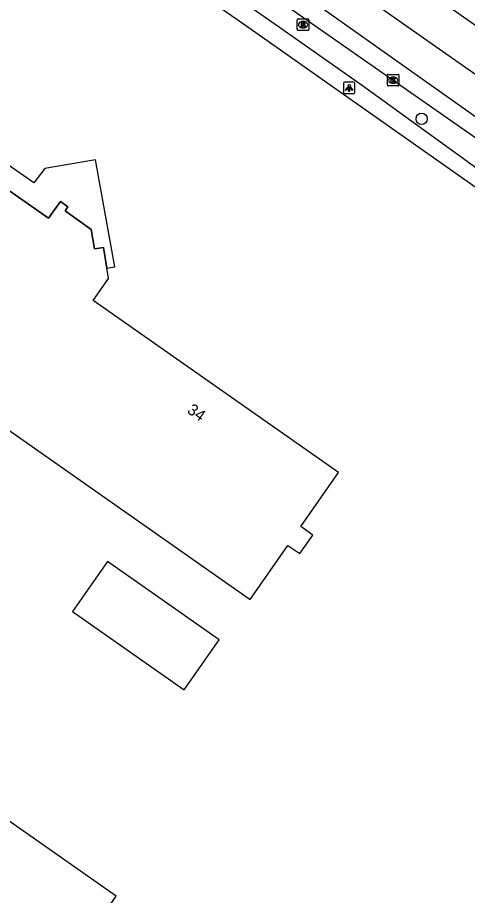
# Model space of a CAD drawing. Extents: x 155018 to 156648, y 383980 to 385733.
# Drawn here: x 155434.7 to 155473.7, y 385174.7 to 385250.7 of the extents above; entities that cross this region are included whole.
import ezdxf

# ---------------------------------------------------------------- set-up
doc = ezdxf.new("R2010")
doc.units = 0
for name, color, linetype in [('IMGEO_Boom', 7, 'Continuous'), ('IMGEO_Kolk', 7, 'Continuous'), ('IMGEO_Lichtpunt', 7, 'Continuous'), ('IMGEO_OVBaan_gesloten', 7, 'Continuous'), ('IMGEO_Pand', 7, 'Continuous'), ('IMGEO_Pand_nummerreeks', 7, 'Continuous'), ('IMGEO_Pand_overbouw', 7, 'Continuous'), ('IMGEO_Rijbaan_lokaal_gesloten', 7, 'Continuous'), ('IMGEO_Rioolput', 7, 'Continuous'), ('IMGEO_Voetpad_open', 7, 'Continuous')]:
    doc.layers.add(name, color=color, linetype=linetype)

msp = doc.modelspace()

# ---------------------------------------------------------------- linework, layer by layer
at = {"layer": 'IMGEO_Boom'}
msp.add_circle((155469.734, 385241.975), 0.489, dxfattribs=at)
at = {"layer": 'IMGEO_Kolk'}
for p, q in [((155466.764, 385244.9), (155466.764, 385245.752)), ((155466.839, 385245.826), (155467.691, 385245.826)), ((155467.252, 385245.606), (155467.277, 385245.606)), ((155467.765, 385245.752), (155467.765, 385244.9)), ((155467.691, 385244.826), (155466.839, 385244.826)), ((155467.275, 385245.046), (155467.25, 385245.046))]:
    msp.add_line(p, q, dxfattribs=at)
for points in [[(155466.764, 385244.9), (155466.764, 385245.752)], [(155466.839, 385245.826), (155467.691, 385245.826)], [(155467.085, 385245.526), (155467.208, 385245.526), (155467.208, 385245.375), (155467.338, 385245.526), (155467.502, 385245.526), (155467.356, 385245.375), (155467.509, 385245.126), (155467.357, 385245.126), (155467.272, 385245.29), (155467.208, 385245.223), (155467.208, 385245.126), (155467.085, 385245.126), (155467.085, 385245.526)], [(155467.765, 385245.752), (155467.765, 385244.9)], [(155467.691, 385244.826), (155466.839, 385244.826)]]:
    msp.add_lwpolyline(points, dxfattribs=at)
for centre, start, end in [((155466.841, 385245.75), 91.55205, 178.44795), ((155466.841, 385245.75), 91.55205, 178.44795), ((155467.689, 385245.75), 1.55205, 88.44795), ((155467.689, 385245.75), 1.55205, 88.44795), ((155466.841, 385244.902), 181.55205, 268.44795), ((155466.841, 385244.902), 181.55205, 268.44795), ((155467.689, 385244.902), 271.55205, 358.44795), ((155467.689, 385244.902), 271.55205, 358.44795)]:
    msp.add_arc(centre, 0.0765, start, end, dxfattribs=at)
for centre, major_axis, ratio, start_param, end_param in [((155467.251, 385245.326), (-0.387, 0.002), 0.722429, 4.712389, 7.853982), ((155467.276, 385245.326), (-0.39, 0.002), 0.717154, 1.570796, 4.712389)]:
    msp.add_ellipse(centre, major_axis=major_axis, ratio=ratio, start_param=start_param, end_param=end_param, dxfattribs=at)
at = {"layer": 'IMGEO_Lichtpunt'}
for p, q in [((155462.958, 385245.061), (155462.958, 385244.254)), ((155462.958, 385245.061), (155462.958, 385244.254)), ((155463.86, 385245.156), (155463.052, 385245.156)), ((155463.86, 385245.156), (155463.052, 385245.156)), ((155463.954, 385244.254), (155463.954, 385245.061)), ((155463.954, 385244.254), (155463.954, 385245.061)), ((155463.052, 385244.16), (155463.86, 385244.16)), ((155463.052, 385244.16), (155463.86, 385244.16))]:
    msp.add_line(p, q, dxfattribs=at)
for points in [[(155463.332, 385244.725), (155463.371, 385244.697), (155463.183, 385244.435), (155463.145, 385244.462), (155463.332, 385244.725)], [(155463.434, 385244.677), (155463.481, 385244.677), (155463.481, 385244.355), (155463.434, 385244.355), (155463.434, 385244.677)], [(155463.544, 385244.697), (155463.582, 385244.724), (155463.769, 385244.462), (155463.73, 385244.434), (155463.544, 385244.697)]]:
    msp.add_lwpolyline(points, dxfattribs=at)
msp.add_circle((155463.457, 385244.859), 0.0994, dxfattribs=at)
for centre, start, end in [((155463.052, 385245.061), 90, 180), ((155463.052, 385245.061), 90, 180), ((155463.86, 385245.061), 0, 90), ((155463.86, 385245.061), 0, 90), ((155463.052, 385244.254), 180, 270), ((155463.052, 385244.254), 180, 270), ((155463.86, 385244.254), 270, 0), ((155463.86, 385244.254), 270, 360)]:
    msp.add_arc(centre, 0.0946, start, end, dxfattribs=at)
at = {"layer": 'IMGEO_OVBaan_gesloten'}
for points in [[(155434.788, 385277.655), (155445.154, 385270.546), (155474.522, 385250), (155483.762, 385243.536)], [(155432.913, 385274.986), (155468.446, 385250), (155481.766, 385240.688)]]:
    msp.add_lwpolyline(points, dxfattribs=at)
at = {"layer": 'IMGEO_Pand'}
for points in [[(155441.261, 385226.23), (155442.591, 385228.15), (155442.443, 385229.05), (155442.151, 385230.83), (155441.388, 385230.704), (155441.107, 385232.405), (155438.832, 385234.02), (155439.081, 385234.37), (155438.441, 385234.81), (155437.391, 385233.36), (155423.311, 385243.23)], [(155430.523, 385217.398), (155454.872, 385200.35), (155458.13, 385205.01), (155459.18, 385204.32), (155460.31, 385205.93), (155459.27, 385206.67), (155462.53, 385211.34), (155441.261, 385226.23)], [(155439.481, 385199.296), (155449.162, 385192.518), (155452.199, 385196.856), (155442.519, 385203.634), (155439.481, 385199.296)], [(155442.008, 385172.848), (155443.274, 385174.657), (155413.901, 385195.202), (155370.632, 385133.346), (155367.766, 385129.249), (155364.489, 385131.542), (155359.431, 385135.082), (155348.617, 385119.628), (155349.496, 385119.02), (155349.893, 385116.961), (155349.266, 385116.068), (155368.071, 385102.911), (155368.632, 385103.714), (155385.157, 385092.221), (155424.544, 385148.026), (155428.297, 385153.343)]]:
    msp.add_lwpolyline(points, dxfattribs=at)
at = {"layer": 'IMGEO_Pand_overbouw'}
msp.add_lwpolyline([(155442.443, 385229.05), (155443.141, 385229.16), (155441.481, 385238.42), (155437.071, 385237.68), (155436.131, 385236.42), (155424.321, 385244.66), (155423.311, 385243.23), (155437.391, 385233.36), (155438.441, 385234.81), (155439.081, 385234.37), (155438.832, 385234.02), (155441.107, 385232.405), (155441.388, 385230.704), (155442.151, 385230.83)], close=True, dxfattribs=at)
at = {"layer": 'IMGEO_Rijbaan_lokaal_gesloten'}
for points in [[(155431.663, 385273.213), (155433.364, 385271.333), (155433.769, 385270.941), (155434.968, 385270.089), (155475.915, 385241.101)], [(155437.905, 385265.859), (155439.338, 385264.844), (155453.681, 385254.836), (155467.265, 385245.326), (155475.085, 385239.875)]]:
    msp.add_lwpolyline(points, dxfattribs=at)
at = {"layer": 'IMGEO_Rioolput'}
for p, q in [((155458.958, 385249.713), (155458.958, 385250.565)), ((155459.033, 385250.639), (155459.885, 385250.639)), ((155459.446, 385250.419), (155459.471, 385250.419)), ((155459.959, 385250.565), (155459.959, 385249.713)), ((155459.885, 385249.639), (155459.033, 385249.639)), ((155459.469, 385249.859), (155459.444, 385249.859))]:
    msp.add_line(p, q, dxfattribs=at)
for points in [[(155458.958, 385249.713), (155458.958, 385250.565)], [(155459.033, 385250.639), (155459.885, 385250.639)], [(155459.547, 385250.337), (155459.295, 385250.339), (155459.295, 385249.939)], [(155459.295, 385249.939), (155459.419, 385249.939), (155459.419, 385250.101), (155459.43, 385250.101)], [(155459.473, 385250.258), (155459.419, 385250.258), (155459.419, 385250.177)], [(155459.419, 385250.177), (155459.471, 385250.177)], [(155459.959, 385250.565), (155459.959, 385249.713)], [(155459.885, 385249.639), (155459.033, 385249.639)], [(155459.477, 385250.072), (155459.548, 385249.939), (155459.688, 385249.939), (155459.623, 385250.065)]]:
    msp.add_lwpolyline(points, dxfattribs=at)
for centre, radius, start, end in [((155459.035, 385250.563), 0.0765, 91.55205, 178.44795), ((155459.035, 385250.563), 0.0765, 91.55205, 178.44795), ((155459.429, 385250.048), 0.0533, 26.02933, 88.69889), ((155459.455, 385250.366), 0.19, 274.7715, 282.96867), ((155459.479, 385250.162), 0.0964, 77.00612, 93.18647), ((155459.493, 385250.219), 0.0378, 276.66336, 79.67722), ((155459.546, 385250.227), 0.109, 350.36119, 89.41601), ((155459.544, 385250.227), 0.112, 277.58423, 350.98172), ((155459.528, 385250.012), 0.108, 29.51342, 73.79051), ((155459.883, 385250.563), 0.0765, 1.55205, 88.44795), ((155459.883, 385250.563), 0.0765, 1.55205, 88.44795), ((155459.035, 385249.715), 0.0765, 181.55205, 268.44795), ((155459.035, 385249.715), 0.0765, 181.55205, 268.44795), ((155459.883, 385249.715), 0.0765, 271.55205, 358.44795), ((155459.883, 385249.715), 0.0765, 271.55205, 358.44795)]:
    msp.add_arc(centre, radius, start, end, dxfattribs=at)
for centre, major_axis, ratio, start_param, end_param in [((155459.445, 385250.139), (-0.387, 0.002), 0.722429, 4.712389, 7.853982), ((155459.47, 385250.139), (-0.39, 0.002), 0.717154, 1.570796, 4.712389)]:
    msp.add_ellipse(centre, major_axis=major_axis, ratio=ratio, start_param=start_param, end_param=end_param, dxfattribs=at)
at = {"layer": 'IMGEO_Voetpad_open'}
for points in [[(155416.844, 385276.273), (155418.525, 385275.088), (155430.291, 385266.788), (155435.607, 385263.049), (155435.813, 385263.317), (155436.277, 385262.901), (155443.177, 385257.98), (155454.592, 385250), (155487.807, 385226.648)], [(155484.282, 385230.934), (155474.511, 385237.675), (155464.606, 385244.845), (155457.427, 385249.874), (155453.798, 385252.416), (155436.84, 385264.295), (155437.905, 385265.859)]]:
    msp.add_lwpolyline(points, dxfattribs=at)

# ---------------------------------------------------------------- texts
at = {"layer": 'IMGEO_Pand_nummerreeks'}
msp.add_text('34', height=1, rotation=325.00374, dxfattribs=at).set_placement((155449.337, 385216.572))

doc.saveas('drawing.dxf')
